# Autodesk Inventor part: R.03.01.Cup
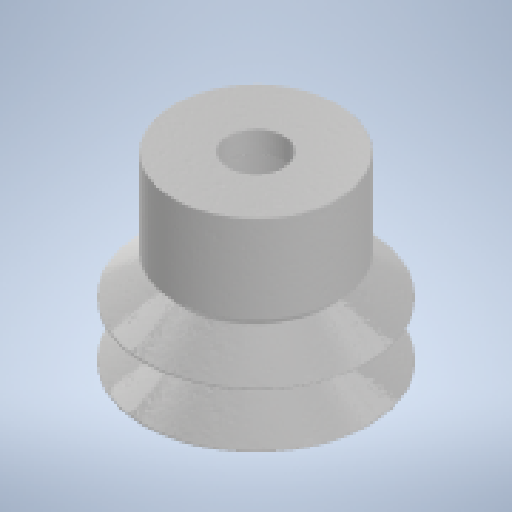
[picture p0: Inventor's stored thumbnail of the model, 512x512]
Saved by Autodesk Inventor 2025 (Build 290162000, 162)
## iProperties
Created: 2021-02
Part Number: R.03.01.Cup
Material: PET Plastic
Document SubType Name: Modeling
Designer: Михальчик
Density: 1.541 g/cm^3
Appearance: Bianco
Author: Михальчик
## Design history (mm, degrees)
sketch "Sketch1"
  geometry: L1 (0, -10.25)-(2.5, -6.5); L2 (2.5, -6.5)-(5, -10.25); L3 (5, -10.25)-(7.5, -6.5); L4 (7.5, -6.5)-(8.5, -7.5); L5 (8.5, -7.5)-(16.5, -7.5); L6 (16.5, -7.5)-(16.5, -2.5); L7 (16.5, -2.5)-(14.5, -2.5); L8 (14.5, -2.5)-(14.5, -3.5); L9 (14.5, -3.5)-(10.75, -3.5); L10 (10.75, -3.5)-(10.75, -2.5); L11 (0, -10.25)-(2.5, -4); L12 (2.5, -4)-(5, -7.75); L13 (5, -7.75)-(7.5, -4); L14 (7.5, -4)-(8.375, -4.875); L15 (8.375, -4.875)-(10.75, -2.5); L16 (0, -10.25)-(5, -10.25); L17 (0, -12.355)-(0, 2.059) reference; L18 (2.5, -4)-(7.5, -4); L19 (5, -7.75)-(5, -10.25); L20 (2.5, -4)-(2.5, -6.5); L21 (7.5, -4)-(7.5, -6.5); L22 (0, 0)-(19.203, 0); L23 (7.5, -6.5)-(5.084, -10.205); L24 (4.916, -10.205)-(2.5, -6.5); L25 (2.5, -6.5)-(0.131, -10.215); L26 (2.5, -4)-(-0.046, -10.123); L27 (0.047, -10.161)-(0, -10.25); A1 r 0.1 centre (5, -10.15) between (4.916, -10.205) and (5.084, -10.205); A2 r 0.1 centre (0.047, -10.161) between (-0.046, -10.123) and (0.131, -10.215)
  constraints: 52 end point, 6 point on circle, 5 perpendicular, 4 horizontal, 4 tangent, 4 vertical, 3 parallel, 3 point on line, 2 centre point, 1 equal radius, 1 other
  dimensions: "d0" = 16.5 distance from line of L1.start L6; "d1" = 7.5 distance from line of L22.start L5; "d2" = 10.25 distance from line of L22.start L16; "d3" = 2.5 distance from line of L22.start L7; "d4" = 3.5 distance from line of L22.start L9; "d5" = 3.75 distance between parallel lines of L8 L10; "d6" = 2 distance between parallel lines of L6 L8; "d7" = 135 deg angle of L5 L4; "d8" = 4 distance from line of L22.start L18; "d9" = 2.5 distance from line of L17 L11.end; "d10" = 5 distance of L11.end L13.end; "d11" = 5 distance of L1.start L2.end; "d12" = 6.5 vertical distance of L22.start L1.end; "d14" = 0.1 radius of A1
revolve "Revolution1" sketch "Sketch1" stored, may be unused: angle "d13" = 90 deg
fillet "Fillet1" dims "d15" = 0.1
body "Solid1"
